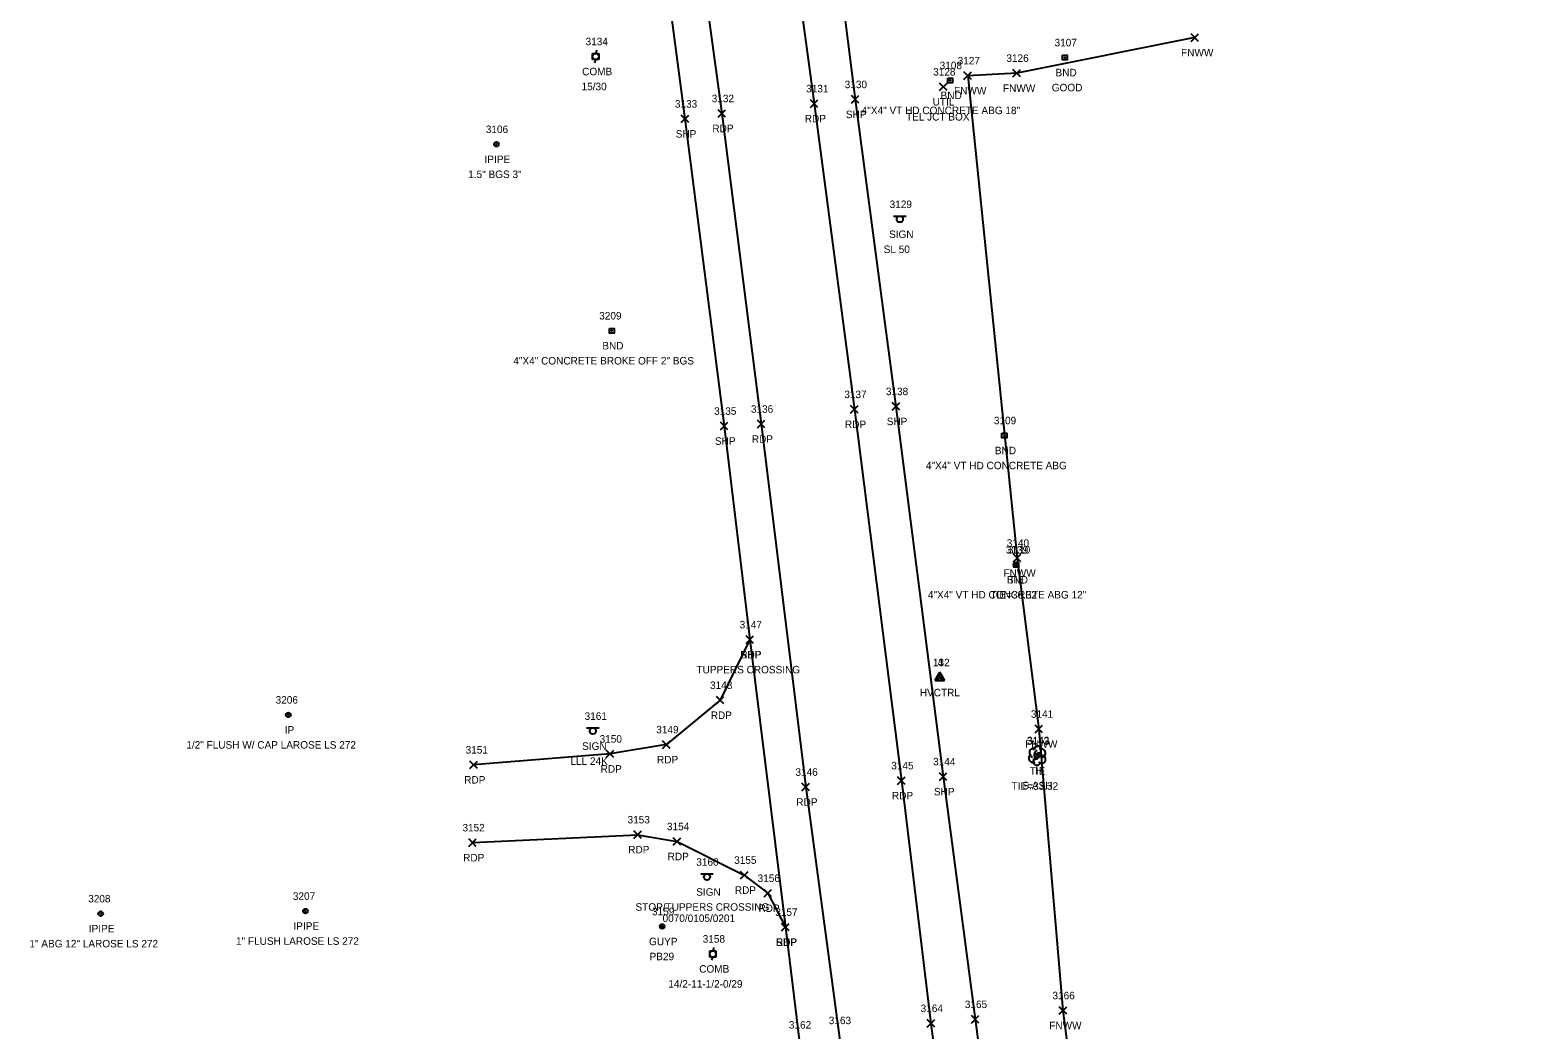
# Model space of a CAD drawing. Extents: x 1443071 to 1445292, y 614024 to 622563.
# Drawn here: x 1444133.7 to 1444535.7, y 616767.9 to 617034.6 of the extents above; entities that cross this region are included whole.
import ezdxf

# ---------------------------------------------------------------- set-up
doc = ezdxf.new("R2010")
doc.units = 0
for name, color, linetype in [('C_A', 7, 'Continuous'), ('C_C', 7, 'Continuous'), ('C_I', 7, 'Continuous'), ('CBP', 7, 'Continuous'), ('CPSM', 7, 'Continuous'), ('L_A', 7, 'Continuous'), ('L_C', 7, 'Continuous'), ('L_I', 7, 'Continuous'), ('L_TIC', 7, 'Continuous'), ('LFNC', 7, 'Continuous'), ('LTD', 7, 'Continuous'), ('M_A', 7, 'Continuous'), ('M_C', 7, 'Continuous'), ('M_I', 7, 'Continuous'), ('MHBP', 7, 'Continuous'), ('MPIP', 7, 'Continuous'), ('MPIR', 7, 'Continuous'), ('P_A', 7, 'Continuous'), ('P_C', 7, 'Continuous'), ('P_I', 7, 'Continuous'), ('P_TIC', 7, 'Continuous'), ('PET', 7, 'Continuous'), ('PSP', 7, 'Continuous'), ('S_A', 7, 'Continuous'), ('S_C', 7, 'Continuous'), ('S_I', 7, 'Continuous'), ('SSGN', 7, 'Continuous'), ('U_A', 7, 'Continuous'), ('U_C', 7, 'Continuous'), ('U_I', 7, 'Continuous'), ('UDEFAULT', 7, 'Continuous'), ('UP', 7, 'Continuous'), ('UPGW', 7, 'Continuous')]:
    doc.layers.add(name, color=color, linetype=linetype)

msp = doc.modelspace()

# ---------------------------------------------------------------- linework, layer by layer
at = {"layer": 'CBP'}
for centre, radius in [((1444396.55, 616891.97), 0.625), ((1444396.55, 616891.97), 0.0833), ((1444402.14, 616840.97), 0.625), ((1444402.14, 616840.97), 0.0833)]:
    msp.add_circle(centre, radius, dxfattribs=at)
at = {"layer": 'CPSM'}
for p, q in [((1444374.95, 616861.18), (1444376.2, 616863.35)), ((1444374.95, 616861.16), (1444376.2, 616863.33)), ((1444374.95, 616861.18), (1444376.2, 616861.91)), ((1444374.95, 616861.16), (1444376.2, 616861.88)), ((1444374.95, 616861.18), (1444377.45, 616861.18)), ((1444374.95, 616861.16), (1444377.45, 616861.16)), ((1444377.45, 616861.18), (1444376.2, 616863.35)), ((1444376.2, 616861.91), (1444376.2, 616863.35)), ((1444377.45, 616861.16), (1444376.2, 616863.33)), ((1444376.2, 616861.88), (1444376.2, 616863.33)), ((1444376.2, 616861.91), (1444376.2, 616861.91)), ((1444376.2, 616861.91), (1444377.45, 616861.18)), ((1444376.2, 616861.88), (1444376.2, 616861.88)), ((1444376.2, 616861.88), (1444377.45, 616861.16))]:
    msp.add_line(p, q, dxfattribs=at)
at = {"layer": 'L_TIC'}
for points in [[(1444443.21, 617031.59), (1444445.21, 617033.59)], [(1444445.21, 617031.59), (1444443.21, 617033.59)], [(1444382.68, 617021.43), (1444384.68, 617023.43)], [(1444384.68, 617021.43), (1444382.68, 617023.43)], [(1444395.73, 617022.1), (1444397.73, 617024.1)], [(1444397.73, 617022.1), (1444395.73, 617024.1)], [(1444395.85, 616892.79), (1444397.85, 616894.79)], [(1444397.85, 616892.79), (1444395.85, 616894.79)], [(1444401.65, 616847.17), (1444403.65, 616849.17)], [(1444403.65, 616847.17), (1444401.65, 616849.17)], [(1444408.06, 616772.1), (1444410.06, 616774.1)], [(1444410.06, 616772.1), (1444408.06, 616774.1)]]:
    msp.add_lwpolyline(points, dxfattribs=at)
at = {"layer": 'LFNC'}
msp.add_lwpolyline([(1444444.21, 617032.59), (1444396.73, 617023.1), (1444383.68, 617022.43), (1444396.85, 616893.79), (1444402.65, 616848.17), (1444409.06, 616773.1), (1444419.22, 616694.29), (1444436.3, 616566.7), (1444446.44, 616488.05), (1444452.89, 616451.02), (1444456.99, 616417.96)], dxfattribs=at)
at = {"layer": 'LTD'}
msp.add_line((1444402.18, 616841.12), (1444402.18, 616841.12), dxfattribs=at)
msp.add_line((1444402.18, 616841.12), (1444402.18, 616841.12), dxfattribs=at)
msp.add_arc((1444402.23, 616842.55), 1.05, 335.5272, 180.9563, dxfattribs=at)
for centre, major_axis, ratio, start_param, end_param in [((1444401.1, 616840.41), (0.58, -1.04), 0.959034, 3.141593, 6.283185), ((1444401.39, 616841.78), (1.21, -0.51), 0.895232, 1.570796, 4.712389), ((1444401.72, 616840.37), (-0.625, -0.083), 0.423636, 0, 3.141593), ((1444401.97, 616841.57), (-0.208, -0.792), 0.645439, 3.141593, 6.283185), ((1444402.68, 616840.95), (-0.5, 0.667), 0.989748, 3.141593, 6.283185), ((1444403.18, 616840.28), (-1.09, 0.79), 0.841452, 1.570796, 4.712389), ((1444403.22, 616841.7), (-1.14, -0.48), 0.949671, 1.570796, 4.712389), ((1444402.18, 616839.62), (0.26, 1.06), 0.942809, 1.570796, 4.712389)]:
    msp.add_ellipse(centre, major_axis=major_axis, ratio=ratio, start_param=start_param, end_param=end_param, dxfattribs=at)
at = {"layer": 'MHBP'}
for points in [[(1444408.97, 617027.88), (1444410.22, 617027.88), (1444410.22, 617026.63), (1444408.97, 617026.63)], [(1444378.34, 617021.79), (1444379.59, 617021.79), (1444379.59, 617020.54), (1444378.34, 617020.54)], [(1444288.14, 616955.02), (1444289.39, 616955.02), (1444289.39, 616953.77), (1444288.14, 616953.77)], [(1444392.81, 616927.09), (1444394.06, 616927.09), (1444394.06, 616925.84), (1444392.81, 616925.84)], [(1444395.98, 616892.61), (1444397.23, 616892.61), (1444397.23, 616891.36), (1444395.98, 616891.36)]]:
    msp.add_lwpolyline(points, close=True, dxfattribs=at)
for centre in [(1444409.6, 617027.26), (1444378.96, 617021.17), (1444288.76, 616954.4), (1444393.43, 616926.46), (1444396.61, 616891.99)]:
    msp.add_circle(centre, 0.0833, dxfattribs=at)
at = {"layer": 'MPIP'}
for centre, radius in [((1444258.01, 617004.13), 0.625), ((1444258.01, 617004.13), 0.0833), ((1444207.07, 616799.62), 0.625), ((1444152.48, 616798.93), 0.625), ((1444152.48, 616798.93), 0.0833), ((1444207.07, 616799.62), 0.0833)]:
    msp.add_circle(centre, radius, dxfattribs=at)
at = {"layer": 'MPIR'}
for radius in [0.625, 0.0833]:
    msp.add_circle((1444202.52, 616851.95), radius, dxfattribs=at)
at = {"layer": 'P_TIC'}
for points in [[(1444317.1, 617011.36), (1444319.1, 617013.36)], [(1444319.1, 617011.36), (1444317.1, 617013.36)], [(1444341.74, 617013.98), (1444343.74, 617015.98)], [(1444343.74, 617013.98), (1444341.74, 617015.98)], [(1444352.65, 617015.1), (1444354.65, 617017.1)], [(1444354.65, 617015.1), (1444352.65, 617017.1)], [(1444307.28, 617009.91), (1444309.28, 617011.91)], [(1444309.28, 617009.91), (1444307.28, 617011.91)], [(1444352.45, 616932.43), (1444354.45, 616934.43)], [(1444354.45, 616932.43), (1444352.45, 616934.43)], [(1444363.55, 616933.22), (1444365.55, 616935.22)], [(1444365.55, 616933.22), (1444363.55, 616935.22)], [(1444317.74, 616927.98), (1444319.74, 616929.98)], [(1444319.74, 616927.98), (1444317.74, 616929.98)], [(1444327.61, 616928.53), (1444329.61, 616930.53)], [(1444329.61, 616928.53), (1444327.61, 616930.53)], [(1444324.56, 616871.02), (1444326.56, 616873.02)], [(1444326.56, 616871.02), (1444324.56, 616873.02)], [(1444324.56, 616871.02), (1444326.56, 616873.02)], [(1444326.56, 616871.02), (1444324.56, 616873.02)], [(1444316.67, 616854.86), (1444318.67, 616856.86)], [(1444318.67, 616854.86), (1444316.67, 616856.86)], [(1444302.33, 616843.02), (1444304.33, 616845.02)], [(1444304.33, 616843.02), (1444302.33, 616845.02)], [(1444287.3, 616840.54), (1444289.3, 616842.54)], [(1444289.3, 616840.54), (1444287.3, 616842.54)], [(1444250.93, 616837.63), (1444252.93, 616839.63)], [(1444252.93, 616837.63), (1444250.93, 616839.63)], [(1444376.14, 616834.48), (1444378.14, 616836.48)], [(1444378.14, 616834.48), (1444376.14, 616836.48)], [(1444339.48, 616831.7), (1444341.48, 616833.7)], [(1444341.48, 616831.7), (1444339.48, 616833.7)], [(1444364.99, 616833.42), (1444366.99, 616835.42)], [(1444366.99, 616833.42), (1444364.99, 616835.42)], [(1444294.66, 616819), (1444296.66, 616821)], [(1444296.66, 616819), (1444294.66, 616821)], [(1444250.65, 616816.87), (1444252.65, 616818.87)], [(1444252.65, 616816.87), (1444250.65, 616818.87)], [(1444305.17, 616817.18), (1444307.17, 616819.18)], [(1444307.17, 616817.18), (1444305.17, 616819.18)], [(1444323.09, 616808.22), (1444325.09, 616810.22)], [(1444325.09, 616808.22), (1444323.09, 616810.22)], [(1444329.39, 616803.38), (1444331.39, 616805.38)], [(1444331.39, 616803.38), (1444329.39, 616805.38)], [(1444334.05, 616794.34), (1444336.05, 616796.34)], [(1444336.05, 616794.34), (1444334.05, 616796.34)], [(1444334.05, 616794.34), (1444336.05, 616796.34)], [(1444336.05, 616794.34), (1444334.05, 616796.34)], [(1444372.87, 616768.68), (1444374.87, 616770.68)], [(1444374.87, 616768.68), (1444372.87, 616770.68)], [(1444384.64, 616769.75), (1444386.64, 616771.75)], [(1444386.64, 616769.75), (1444384.64, 616771.75)]]:
    msp.add_lwpolyline(points, dxfattribs=at)
at = {"layer": 'PET'}
for points in [[(1444290.04, 617226.49), (1444293.29, 617200.68), (1444305.86, 617102.26), (1444318.1, 617012.36), (1444328.61, 616929.53), (1444340.48, 616832.7), (1444349.36, 616766.46), (1444359.48, 616687.73), (1444375.76, 616559.26), (1444386.72, 616474.82), (1444392.98, 616424.11), (1444399.64, 616374.74), (1444405.35, 616331.68), (1444416.25, 616246.74), (1444430.45, 616134.64), (1444440.68, 616052.2), (1444460.71, 615897.87), (1444469.48, 615825.17), (1444479.32, 615749.85), (1444490.82, 615663.43), (1444501.1, 615593.99)], [(1444314.9, 617227.6), (1444331.28, 617099.37), (1444342.74, 617014.98), (1444353.45, 616933.43), (1444365.99, 616834.42), (1444373.87, 616769.68), (1444384.25, 616690.54), (1444399.86, 616561.36), (1444411.32, 616477.78), (1444418.43, 616426.72), (1444433.04, 616320.39), (1444440.5, 616248.61), (1444455.15, 616137.88), (1444465.57, 616054.84), (1444485.3, 615900.9), (1444494.14, 615826.26), (1444503.74, 615751.94), (1444515.41, 615666.64), (1444525.64, 615597.72)], [(1444325.56, 616872.02), (1444317.67, 616855.86), (1444303.33, 616844.02), (1444288.3, 616841.54), (1444251.93, 616838.63)], [(1444251.65, 616817.87), (1444295.66, 616820), (1444306.17, 616818.18), (1444324.09, 616809.22), (1444330.39, 616804.38), (1444335.05, 616795.34)]]:
    msp.add_lwpolyline(points, dxfattribs=at)
at = {"layer": 'PSP'}
for points in [[(1444325.72, 617229.34), (1444331.18, 617190.03), (1444341.63, 617111.11), (1444353.65, 617016.1), (1444364.55, 616934.22), (1444377.14, 616835.48), (1444385.64, 616770.75), (1444395.97, 616692.96), (1444412.43, 616562.03), (1444423.01, 616481.11), (1444430.88, 616420.51), (1444443.11, 616323.39), (1444448.99, 616268.44), (1444454, 616230.8), (1444465.61, 616141.36), (1444476.5, 616056.13), (1444483.28, 615998.72), (1444489.46, 615946.55), (1444495.54, 615902.14), (1444505.18, 615827.19), (1444514.81, 615753.2), (1444525.85, 615667.7), (1444535.69, 615600.77)], [(1444280.5, 617226.12), (1444283.66, 617200.61), (1444293.17, 617127.11), (1444296.38, 617100.83), (1444308.28, 617010.91), (1444318.74, 616928.98), (1444325.56, 616872.02), (1444335.05, 616795.34), (1444338.72, 616765.27), (1444349.45, 616686.56), (1444353.22, 616653.3), (1444364.91, 616559.25), (1444375.85, 616473.62), (1444383.24, 616422.24), (1444388.01, 616382.64), (1444395.12, 616329.81), (1444406.01, 616244.88), (1444420.16, 616134.13), (1444430.49, 616051.12), (1444450.17, 615896.86), (1444459.96, 615823.48), (1444469.66, 615749), (1444481.34, 615661.86), (1444491.6, 615592.34)]]:
    msp.add_lwpolyline(points, dxfattribs=at)
at = {"layer": 'SSGN'}
for p, q in [((1444363.92, 616984.98), (1444367.25, 616984.98)), ((1444365.57, 616984.15), (1444365.57, 616984.15)), ((1444282.06, 616848.48), (1444285.4, 616848.48)), ((1444283.71, 616847.64), (1444283.71, 616847.64)), ((1444312.5, 616809.57), (1444315.83, 616809.57)), ((1444314.14, 616808.73), (1444314.14, 616808.73))]:
    msp.add_line(p, q, dxfattribs=at)
for centre in [(1444365.57, 616984.15), (1444283.71, 616847.64), (1444314.14, 616808.73)]:
    msp.add_circle(centre, 0.833, dxfattribs=at)
at = {"layer": 'UDEFAULT'}
for points in [[(1444376.15, 617018.47), (1444378.15, 617020.47)], [(1444378.15, 617018.47), (1444376.15, 617020.47)]]:
    msp.add_lwpolyline(points, dxfattribs=at)
at = {"layer": 'UP'}
for p, q in [((1444283.64, 617026.71), (1444283.64, 617028.38)), ((1444283.64, 617028.38), (1444285.31, 617028.38)), ((1444285.31, 617026.71), (1444283.64, 617026.71)), ((1444284.23, 617025.88), (1444284.48, 617026.71)), ((1444284.73, 617029.21), (1444284.48, 617028.38)), ((1444284.48, 617027.54), (1444284.48, 617027.54)), ((1444285.31, 617028.38), (1444285.31, 617026.71)), ((1444314.87, 616787.37), (1444314.87, 616789.03)), ((1444314.87, 616789.03), (1444316.54, 616789.03)), ((1444315.95, 616789.87), (1444315.7, 616789.03)), ((1444315.7, 616788.2), (1444315.7, 616788.2)), ((1444316.54, 616789.03), (1444316.54, 616787.37)), ((1444316.54, 616787.37), (1444314.87, 616787.37)), ((1444315.45, 616786.53), (1444315.7, 616787.37))]:
    msp.add_line(p, q, dxfattribs=at)
for centre in [(1444284.48, 617027.54), (1444315.7, 616788.2)]:
    msp.add_circle(centre, 0.833, dxfattribs=at)
at = {"layer": 'UPGW'}
for radius in [0.625, 0.0833]:
    msp.add_circle((1444302.2, 616795.51), radius, dxfattribs=at)

# ---------------------------------------------------------------- texts
at = {"layer": 'C_A'}
for s, p in [('TIE', (1444394.63, 616886.97)), ('HVCTRL', (1444370.89, 616856.91)), ('HVCTRL', (1444370.9, 616856.88)), ('TIE', (1444400.22, 616835.97))]:
    msp.add_text(s, height=2, dxfattribs=at).set_placement(p)
at = {"layer": 'C_C'}
for s, p in [('TIE=36.32', (1444389.73, 616882.97)), ('TIE=33.32', (1444395.37, 616831.97))]:
    msp.add_text(s, height=2, dxfattribs=at).set_placement(p)
at = {"layer": 'C_I'}
for s, p in [('3139', (1444393.85, 616894.97)), ('132', (1444374.4, 616864.91)), ('4', (1444375.64, 616864.88)), ('3143', (1444399.45, 616843.97))]:
    msp.add_text(s, height=2, dxfattribs=at).set_placement(p)
at = {"layer": 'L_A'}
for s, p in [('FNWW', (1444440.56, 617027.59)), ('FNWW', (1444380.03, 617017.43)), ('FNWW', (1444393.08, 617018.1)), ('FNWW', (1444393.2, 616888.79)), ('FNWW', (1444398.99, 616843.17)), ('H', (1444401.62, 616836.12)), ('FNWW', (1444405.41, 616768.1))]:
    msp.add_text(s, height=2, dxfattribs=at).set_placement(p)
at = {"layer": 'L_C'}
msp.add_text('S.ASH', height=2, dxfattribs=at).set_placement((1444398.26, 616832.12))
at = {"layer": 'L_I'}
for s, p in [('3127', (1444380.99, 617025.43)), ('3126', (1444393.99, 617026.1)), ('3140', (1444394.08, 616896.79)), ('3141', (1444400.52, 616851.17)), ('3142', (1444399.49, 616844.12)), ('3166', (1444406.27, 616776.1))]:
    msp.add_text(s, height=2, dxfattribs=at).set_placement(p)
at = {"layer": 'M_A'}
for s, p in [('BND', (1444407.09, 617022.26)), ('BND', (1444376.45, 617016.17)), ('IPIPE', (1444254.84, 616999.13)), ('BND', (1444286.25, 616949.4)), ('BND', (1444390.92, 616921.46)), ('BND', (1444394.1, 616886.99)), ('IP', (1444201.57, 616846.95)), ('IPIPE', (1444203.9, 616794.62)), ('IPIPE', (1444149.32, 616793.93))]:
    msp.add_text(s, height=2, dxfattribs=at).set_placement(p)
at = {"layer": 'M_C'}
for s, p in [('GOOD', (1444406.08, 617018.26)), ('4"X4" VT HD CONCRETE ABG 18"', (1444355.41, 617012.17)), ('1.5" BGS 3"', (1444250.48, 616995.13)), ('4"X4" CONCRETE BROKE OFF 2" BGS', (1444262.51, 616945.4)), ('4"X4" VT HD CONCRETE ABG', (1444372.53, 616917.46)), ('4"X4" VT HD CONCRETE ABG 12"', (1444373.05, 616882.99)), ('1/2" FLUSH W/ CAP LAROSE LS 272', (1444175.32, 616842.95)), ('1" FLUSH LAROSE LS 272', (1444188.58, 616790.62)), ('1" ABG 12" LAROSE LS 272', (1444133.48, 616789.93))]:
    msp.add_text(s, height=2, dxfattribs=at).set_placement(p)
at = {"layer": 'M_I'}
for s, p in [('3107', (1444406.83, 617030.26)), ('3108', (1444376.19, 617024.17)), ('3106', (1444255.18, 617007.13)), ('3209', (1444285.42, 616957.4)), ('3109', (1444390.65, 616929.46)), ('3110', (1444394.4, 616894.99)), ('3206', (1444199.13, 616854.95)), ('3207', (1444203.73, 616802.62)), ('3208', (1444149.15, 616801.93))]:
    msp.add_text(s, height=2, dxfattribs=at).set_placement(p)
at = {"layer": 'P_A'}
for s, p in [('RDP', (1444315.59, 617007.36)), ('RDP', (1444340.23, 617009.98)), ('SHP', (1444351.18, 617011.1)), ('SHP', (1444305.82, 617005.91)), ('RDP', (1444350.94, 616928.43)), ('SHP', (1444362.08, 616929.22)), ('SHP', (1444316.28, 616923.98)), ('RDP', (1444326.1, 616924.53)), ('SHP', (1444323.09, 616867.02)), ('RDP', (1444323.04, 616867.02)), ('RDP', (1444315.16, 616850.86)), ('RDP', (1444300.82, 616839.02)), ('RDP', (1444285.79, 616836.54)), ('RDP', (1444249.42, 616833.63)), ('SHP', (1444374.67, 616830.48)), ('RDP', (1444337.97, 616827.7)), ('RDP', (1444363.47, 616829.42)), ('RDP', (1444293.15, 616815)), ('RDP', (1444249.13, 616812.87)), ('RDP', (1444303.66, 616813.18)), ('RDP', (1444321.58, 616804.22)), ('RDP', (1444327.88, 616799.38)), ('SHP', (1444332.58, 616790.34)), ('RDP', (1444332.54, 616790.34))]:
    msp.add_text(s, height=2, dxfattribs=at).set_placement(p)
at = {"layer": 'P_C'}
msp.add_text('TUPPERS CROSSING', height=2, dxfattribs=at).set_placement((1444311.34, 616863.02))
at = {"layer": 'P_I'}
for s, p in [('3132', (1444315.41, 617015.36)), ('3131', (1444340.61, 617017.98)), ('3130', (1444350.87, 617019.1)), ('3133', (1444305.59, 617013.91)), ('3137', (1444350.76, 616936.43)), ('3138', (1444361.85, 616937.22)), ('3135', (1444316.05, 616931.98)), ('3136', (1444325.86, 616932.53)), ('3147', (1444322.86, 616875.02)), ('3147', (1444322.86, 616875.02)), ('3148', (1444314.97, 616858.86)), ('3149', (1444300.63, 616847.02)), ('3150', (1444285.52, 616844.54)), ('3151', (1444249.8, 616841.63)), ('3144', (1444374.44, 616838.48)), ('3146', (1444337.74, 616835.7)), ('3145', (1444363.29, 616837.42)), ('3153', (1444292.97, 616823)), ('3152', (1444248.95, 616820.87)), ('3154', (1444303.48, 616821.18)), ('3155', (1444321.4, 616812.22)), ('3156', (1444327.65, 616807.38)), ('3157', (1444332.35, 616798.34)), ('3157', (1444332.35, 616798.34)), ('3164', (1444371.12, 616772.68)), ('3165', (1444382.9, 616773.75)), ('3162', (1444335.98, 616768.27)), ('3163', (1444346.62, 616769.46))]:
    msp.add_text(s, height=2, dxfattribs=at).set_placement(p)
at = {"layer": 'S_A'}
for p in [(1444362.7, 616979.13), (1444280.85, 616842.62), (1444311.28, 616803.71)]:
    msp.add_text('SIGN', height=2, dxfattribs=at).set_placement(p)
at = {"layer": 'S_C'}
for s, p in [('SL 50', (1444361.26, 616975.13)), ('LLL 24K', (1444277.74, 616838.62)), ('STOP/TUPPERS CROSSING', (1444295.09, 616799.71)), ('0070/0105/0201', (1444302.31, 616796.71))]:
    msp.add_text(s, height=2, dxfattribs=at).set_placement(p)
at = {"layer": 'S_I'}
for s, p in [('3129', (1444362.85, 616987.13)), ('3161', (1444281.52, 616850.62)), ('3160', (1444311.3, 616811.71))]:
    msp.add_text(s, height=2, dxfattribs=at).set_placement(p)
at = {"layer": 'U_A'}
for s, p in [('COMB', (1444280.86, 617022.54)), ('UTIL', (1444374.32, 617014.47)), ('GUYP', (1444298.71, 616790.51)), ('COMB', (1444312.09, 616783.2))]:
    msp.add_text(s, height=2, dxfattribs=at).set_placement(p)
at = {"layer": 'U_C'}
for s, p in [('15/30', (1444280.72, 617018.54)), ('TEL JCT BOX', (1444367.21, 617010.47)), ('PB29', (1444298.84, 616786.51)), ('14/2-11-1/2-0/29', (1444303.85, 616779.2))]:
    msp.add_text(s, height=2, dxfattribs=at).set_placement(p)
at = {"layer": 'U_I'}
for s, p in [('3134', (1444281.78, 617030.54)), ('3128', (1444374.46, 617022.47)), ('3159', (1444299.5, 616798.51)), ('3158', (1444313.01, 616791.2))]:
    msp.add_text(s, height=2, dxfattribs=at).set_placement(p)

doc.saveas('drawing.dxf')
